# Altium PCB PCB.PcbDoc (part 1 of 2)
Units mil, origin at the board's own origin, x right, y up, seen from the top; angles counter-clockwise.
Board outline 4000 x 1900 mil, 2 copper layers (Top Layer, Bottom Layer), stack 62 mil thick; 73 components, 38 nets, 157 pads, 24 vias.
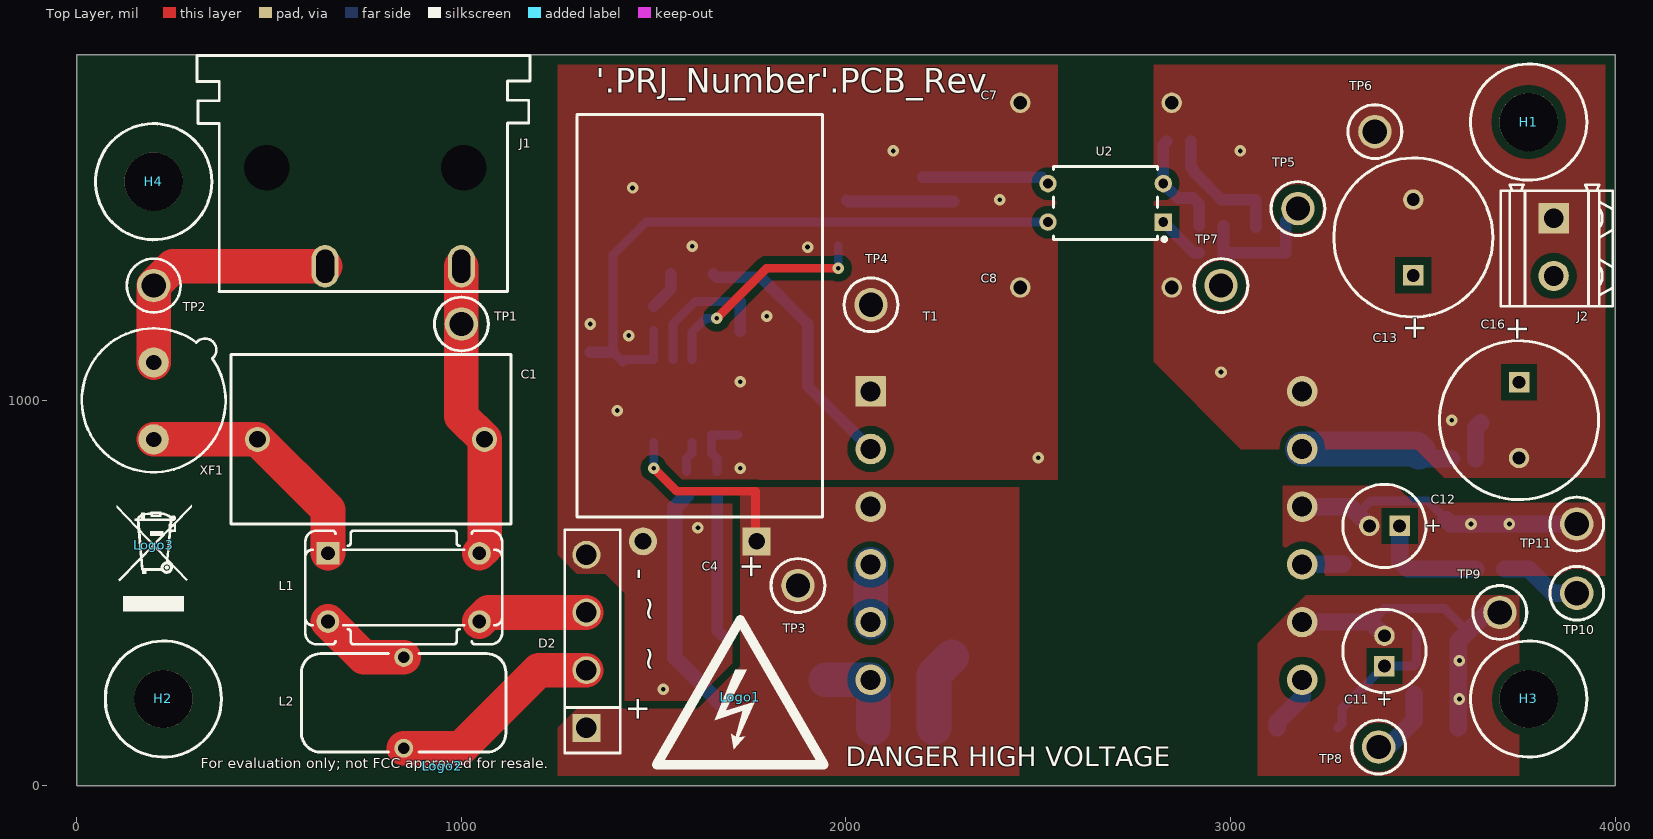
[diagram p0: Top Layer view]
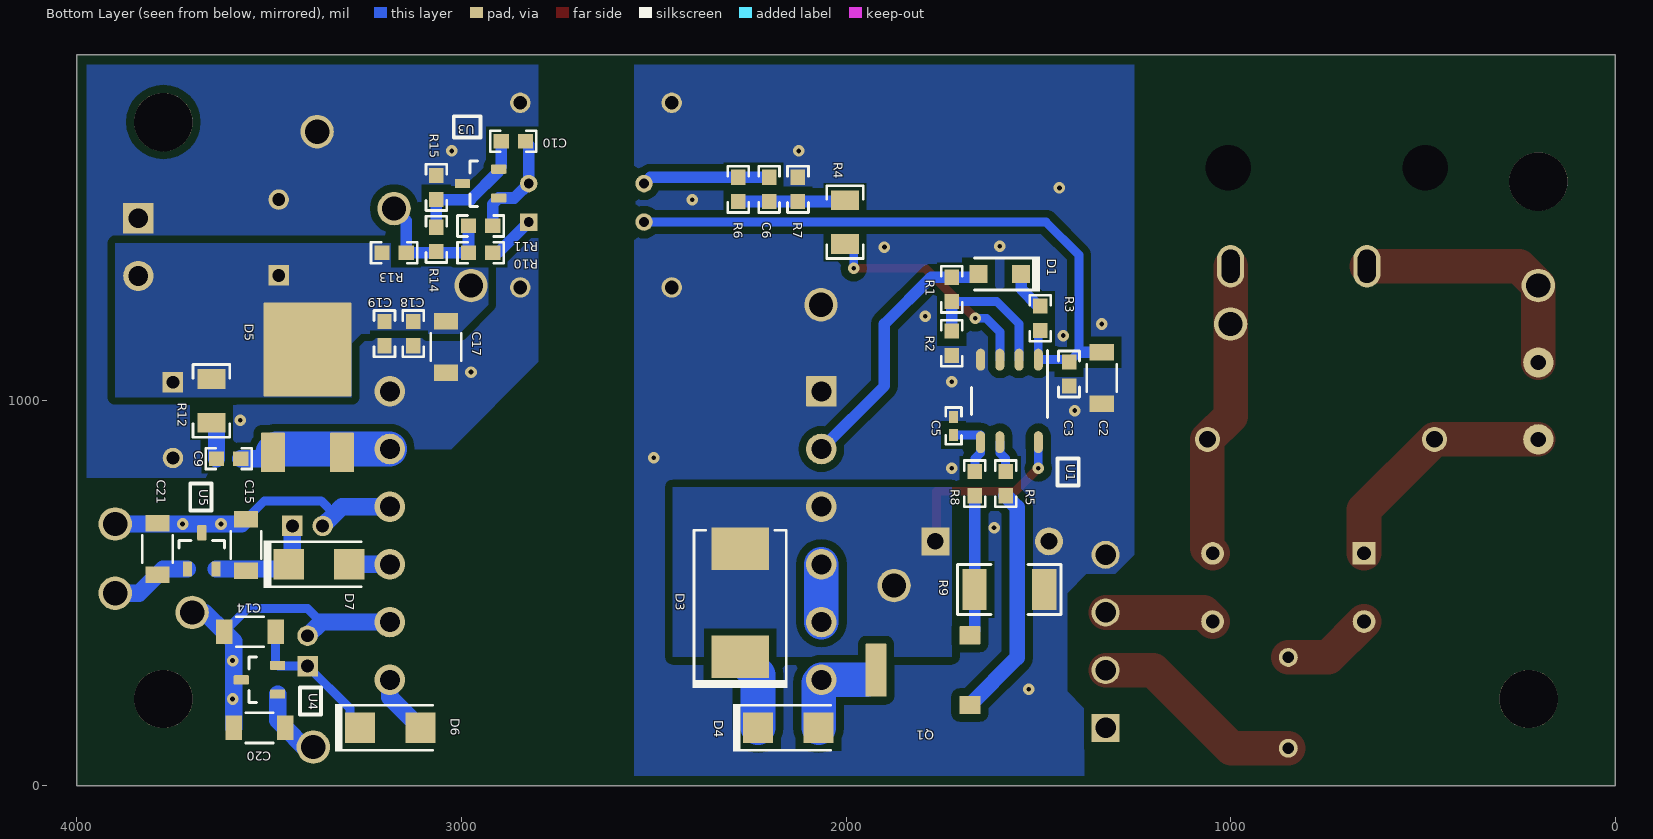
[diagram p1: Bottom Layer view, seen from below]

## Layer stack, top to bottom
Top Solder: solder mask 0.4, Solder Resist, Dk 3.5
Top Layer: signal copper 1.4
Dielectric1: core 59.2, FR-4, Dk 4.8
Bottom Layer: signal copper 1.4
Bottom Solder: solder mask 0.4, Solder Resist, Dk 3.5

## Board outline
0,0 4000,0 4000,1900 0,1900

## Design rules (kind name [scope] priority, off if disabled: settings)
AcuteAngle [All] p1: minimum=4.50000000000000E+0001 checktracksonly=FALSE
AssemblyTestPointUsage [All] p1: valid=2
BoardOutlineClearance BoardOutlineClearance_MountingHoles [OnCopper and InComponentClass('Mounting Holes')] p1: gap=25 ignorepadtopadclearanceinfootprint=FALSE
BoardOutlineClearance BoardOutlineClearance_Poly [OnCopper and InPoly] p2: gap=25 ignorepadtopadclearanceinfootprint=FALSE
BoardOutlineClearance [OnCopper and Not InComponentClass('Logo') and not InComponentClass('FiducialMark') and not InRegion(1000,500,4000,800)] p3: gap=25 ignorepadtopadclearanceinfootprint=FALSE
Clearance Clearance_2 [InNetClass('HV') vs Not InNetClass('HV')] p1: gap=60 ignorepadtopadclearanceinfootprint=FALSE
Clearance Clearance_1 [InNetClass('MV') vs Not InNetClass('MV')] p2: gap=30 ignorepadtopadclearanceinfootprint=FALSE
Clearance Clearance_Keepouts [((IsTrack Or IsArc) And Not InPoly) And IsFree and IsKeepOut vs ((IsTrack Or IsArc) And Not InPoly) And IsFree and IsKeepOut] p3: gap=0 ignorepadtopadclearanceinfootprint=FALSE
Clearance Clearance_BoardEdge_MountingHoles [OnCopper and InComponentClass('Mounting Holes') vs IsKeepOut] p4: gap=40 ignorepadtopadclearanceinfootprint=FALSE except(0: Arc-Hole Track-Hole SMDPad-Hole THPad-Hole Via-Hole Fill-Hole Poly-Hole Region-Hole Text-Hole)
Clearance Clearance_BoardEdge_Poly [OnCopper and InPoly vs IsKeepOut] p5: gap=50 ignorepadtopadclearanceinfootprint=FALSE except(0: Arc-Hole Track-Hole SMDPad-Hole THPad-Hole Via-Hole Fill-Hole Poly-Hole Region-Hole Text-Hole)
Clearance Clearance_BoardEdge [OnCopper and Not InComponentClass('Logo') and not InComponentClass('FiducialMark') and not InRegion(1000,500,4000,800) and Not IsKeepout vs IsKeepOut] p6: gap=50 ignorepadtopadclearanceinfootprint=FALSE
Clearance Clearance_Poly [InPolygon] p7: gap=20 ignorepadtopadclearanceinfootprint=FALSE except(0: Arc-Hole Track-Hole SMDPad-Hole THPad-Hole Via-Hole Fill-Hole Poly-Hole Region-Hole Text-Hole)
Clearance [All] p8: gap=7.87 ignorepadtopadclearanceinfootprint=FALSE except(0: Arc-Hole Track-Hole SMDPad-Hole THPad-Hole Via-Hole Fill-Hole Poly-Hole Region-Hole Text-Hole)
ComponentClearance ComponentClearance_MountingHoles_FiducialMarks [InComponentClass('Mounting Holes') vs InComponentClass('FiducialMark')] p1: gap=20 collisioncheckmode=3 verticalgap=10 showdistances=FALSE
ComponentClearance ComponentClearance_Shunt [InComponentClass('Header') vs InComponentClass('Shunt')] p2: gap=0 collisioncheckmode=3 verticalgap=0 showdistances=FALSE
ComponentClearance ComponentClearance_Logo [InComponentClass('Logo')] p3: gap=5 collisioncheckmode=3 verticalgap=10 showdistances=FALSE
ComponentClearance ComponentClearance_ScrewToNut [(HasFootprint('NY PMS 440 0025 PH')) vs (HasFootprint('Keystone_1902C'))] p4: gap=20 collisioncheckmode=3 verticalgap=100000 showdistances=FALSE
ComponentClearance ComponentClearance_MountingHoles [InComponentClass('Mounting Holes')] p5: gap=20 collisioncheckmode=3 verticalgap=10 showdistances=FALSE
ComponentClearance ComponentClearance_SmallPassives [HasFootprint('0201*') or HasFootprint('0402*') or HasFootprint('0508') or HasFootprint('0603*') or HasFootprint('0612') or HasFootprint('0805*') or HasFootprint('0815*') or HasFootprint('0830*') or HasFootprint('1206*') or HasFootprint('1210*') or HasFootprint('1808*') or HasFootprint('1812*') or HasFootprint('1825*') or HasFootprint('2010*') or HasFootprint('2220*') or HasFootprint('2225*') or HasFootprint('2512*') or HasFootprint('2728*') or HasFootprint('3518*') vs HasFootprint('0201*') or HasFootprint('0402*') or HasFootprint('0508') or HasFootprint('0603*') or HasFootprint('0612') or HasFootprint('0805*') or HasFootprint('0815*') or HasFootprint('0830*') or HasFootprint('1206*') or HasFootprint('1210*') or HasFootprint('1808*') or HasFootprint('1812*') or HasFootprint('1825*') or HasFootprint('2010*') or HasFootprint('2220*') or HasFootprint('2225*') or HasFootprint('2512*') or HasFootprint('2728*') or HasFootprint('3518*')] p6: gap=20 collisioncheckmode=3 verticalgap=20 showdistances=FALSE
ComponentClearance ComponentClearance_THtoSMT [IsThruComponent vs IsSMTComponent] p7: gap=10 collisioncheckmode=3 verticalgap=10 showdistances=FALSE
ComponentClearance ComponentClearance_THtoTH [IsThruComponent vs IsThruComponent] p8: gap=10 collisioncheckmode=3 verticalgap=10 showdistances=FALSE
ComponentClearance [All] p9: gap=10 collisioncheckmode=3 verticalgap=10 showdistances=FALSE
DiffPairsRouting [All] p1: maxlimit=100 minlimit=10 mostfreqgap=10 toplayer_minwidth=15 toplayer_maxwidth=15 toplayer_prefwidth=15 bottomlayer_minwidth=15 bottomlayer_maxwidth=15 bottomlayer_prefwidth=15 maxuncoupledlength=1000
FabricationTestPointUsage TestPointUsage [All] p1: valid=2 allowmultiple=FALSE
FabricationTestpoint Testpoint [All] p1: side=3 testpointundercomponent=TRUE minsize=40 maxsize=100 preferedsize=60 minholesize=0 maxholesize=40 preferedholesize=32 testpointgrid=1 allowsidetop=TRUE allowsidebottom=TRUE usegrid=TRUE gridtolerance=0.01
FanoutControl Fanout_LCC [IsLCC] p1: bgadir=Out bgaviamode=Centered fanoutstyle=Auto fanoutdirection=Alternating viagrid=1 // Fanout_LCC (Default Rule)
FanoutControl Fanout_BGA [IsBGA] p2: bgadir=Out bgaviamode=Centered fanoutstyle=Auto fanoutdirection=Alternating viagrid=1 // Fanout_BGA (Default Rule)
FanoutControl Fanout_Default [All] p4: bgadir=Out bgaviamode=Centered fanoutstyle=Auto fanoutdirection=Alternating viagrid=1 // Fanout_Default (Default Rule)
FanoutControl Fanout_Small [(CompPinCount < 5)] p5: bgadir=Out bgaviamode=Centered fanoutstyle=Auto fanoutdirection=OutThenIn viagrid=1 // Fanout_Small (Default Rule)
Height [All] p1: minheight=0 maxheight=3000 prefheight=500
HoleSize [All] p1: absolutevalues=TRUE maxlimit=251 minlimit=7.87 maxpercent=80.000 minpercent=20.000
MinimumAnnularRing MinimumAnnularRing_ThermalPadVias [IsVia and InAnyComponent] p1: minimumring=5.91
MinimumAnnularRing [All] p2: minimumring=8
MinimumSolderMaskSliver MinimumSolderMaskSliver_Logo [InComponentClass('Logo') vs InComponentClass('Logo')] p1: minsoldermaskwidth=0.7
MinimumSolderMaskSliver [All] p2: minsoldermaskwidth=3.94
PlaneConnect [All] p1: planeconnectstyle=Direct reliefexpansion=10 reliefentries=4 reliefconductorwidth=10 reliefairgap=10
PolygonConnect PolygonConnect_15 [All vs IsNamedPolygon('C109_2') Or  IsNamedPolygon('C107_2') Or  IsNamedPolygon('HV') Or  IsNamedPolygon('Q203_5') Or  IsNamedPolygon('C107_2') Or  IsNamedPolygon('HS') Or  IsNamedPolygon('Q201_5') Or  IsNamedPolygon('Q203_5') Or  IsNamedPolygon('C106_2') Or  IsNamedPolygon('C108_2') Or  IsNamedPolygon('Vout') Or  IsNamedPolygon('Q203_5') Or  IsNamedPolygon('C108_2') Or  IsNamedPolygon('C113_2') Or  IsNamedPolygon('Q203_5') Or  IsNamedPolygon('Q201_5') Or  IsNamedPolygon('C107_2') Or  IsNamedPolygon('C102_1') Or  IsNamedPolygon('SGND') Or  IsNamedPolygon('GND') Or  IsNamedPolygon('SGND') Or  IsNamedPolygon('GND') Or  IsNamedPolygon('IN+') Or  IsNamedPolygon('IN+') Or  IsNamedPolygon('Q201_5') Or  IsNamedPolygon('Q201_5') Or  IsNamedPolygon('SGND') Or  IsNamedPolygon('SGND') Or  IsNamedPolygon('Vout') Or  IsNamedPolygon('Vout') Or  IsNamedPolygon('IN+') Or  IsNamedPolygon('GND') Or  IsNamedPolygon('IN+') Or  IsNamedPolygon('GND')] p1: connectstyle=Direct reliefconductorwidth=10 reliefentries=4 polygonreliefangle="90 Angle" airgapwidth=10
PolygonConnect PolygonConnect_14 [All vs IsNamedPolygon('C106_2') Or  IsNamedPolygon('C107_2') Or  IsNamedPolygon('C107_2') Or  IsNamedPolygon('C107_2') Or  IsNamedPolygon('C102_1') Or  IsNamedPolygon('Q203_5') Or  IsNamedPolygon('Vout') Or  IsNamedPolygon('Q203_5') Or  IsNamedPolygon('Q203_5') Or  IsNamedPolygon('Q201_5') Or  IsNamedPolygon('C108_2') Or  IsNamedPolygon('Q203_5') Or  IsNamedPolygon('HS') Or  IsNamedPolygon('HV') Or  IsNamedPolygon('C108_2') Or  IsNamedPolygon('Q201_5') Or  IsNamedPolygon('C109_2') Or  IsNamedPolygon('Q201_5') Or  IsNamedPolygon('Q201_5') Or  IsNamedPolygon('C113_2')] p2: connectstyle=Direct reliefconductorwidth=10 reliefentries=4 polygonreliefangle="90 Angle" airgapwidth=10
PolygonConnect PolygonConnect_13 [All vs IsNamedPolygon('C102_1') Or  IsNamedPolygon('HV') Or  IsNamedPolygon('C107_2') Or  IsNamedPolygon('C109_2') Or  IsNamedPolygon('C107_2') Or  IsNamedPolygon('C108_2') Or  IsNamedPolygon('C106_2') Or  IsNamedPolygon('C108_2') Or  IsNamedPolygon('C113_2') Or  IsNamedPolygon('C107_2')] p3: connectstyle=Direct reliefconductorwidth=10 reliefentries=4 polygonreliefangle="90 Angle" airgapwidth=10
PolygonConnect PolygonConnect_12 [All vs IsNamedPolygon('C107_2') Or  IsNamedPolygon('C113_2') Or  IsNamedPolygon('C106_2') Or  IsNamedPolygon('C107_2') Or  IsNamedPolygon('C107_2') Or  IsNamedPolygon('C102_1')] p4: connectstyle=Direct reliefconductorwidth=10 reliefentries=4 polygonreliefangle="90 Angle" airgapwidth=10
PolygonConnect PolygonConnect_11 [All vs IsNamedPolygon('C106_2') Or  IsNamedPolygon('C102_1') Or  IsNamedPolygon('C107_2') Or  IsNamedPolygon('C107_2') Or  IsNamedPolygon('C107_2')] p5: connectstyle=Direct reliefconductorwidth=10 reliefentries=4 polygonreliefangle="90 Angle" airgapwidth=10
PolygonConnect PolygonConnect_10 [All vs IsNamedPolygon('C106_2')] p6: connectstyle=Direct reliefconductorwidth=10 reliefentries=4 polygonreliefangle="90 Angle" airgapwidth=10
PolygonConnect PolygonConnect_9 [All vs IsNamedPolygon('C11_1') Or  IsNamedPolygon('Vin') Or  IsNamedPolygon('Vin') Or  IsNamedPolygon('5V') Or  IsNamedPolygon('D6_2') Or  IsNamedPolygon('Q3_3') Or  IsNamedPolygon('GND2') Or  IsNamedPolygon('GND2') Or  IsNamedPolygon('GND') Or  IsNamedPolygon('Q3_4') Or  IsNamedPolygon('12V5') Or  IsNamedPolygon('GND') Or  IsNamedPolygon('12V5') Or  IsNamedPolygon('D3_1')] p7: connectstyle=Direct reliefconductorwidth=10 reliefentries=4 polygonreliefangle="90 Angle" airgapwidth=10
PolygonConnect PolygonConnect_8 [All vs IsNamedPolygon('C11_1') Or  IsNamedPolygon('Vin') Or  IsNamedPolygon('12V5') Or  IsNamedPolygon('Q3_3') Or  IsNamedPolygon('GND2') Or  IsNamedPolygon('GND2') Or  IsNamedPolygon('5V') Or  IsNamedPolygon('Q3_4') Or  IsNamedPolygon('12V5')] p8: connectstyle=Direct reliefconductorwidth=10 reliefentries=4 polygonreliefangle="90 Angle" airgapwidth=10
PolygonConnect PolygonConnect_7 [All vs IsNamedPolygon('GND2') Or  IsNamedPolygon('GND2') Or  IsNamedPolygon('5V') Or  IsNamedPolygon('12V5') Or  IsNamedPolygon('12V5') Or  IsNamedPolygon('C11_1')] p9: connectstyle=Direct reliefconductorwidth=10 reliefentries=4 polygonreliefangle="90 Angle" airgapwidth=10
PolygonConnect PolygonConnect_6 [All vs IsNamedPolygon('GND2') Or  IsNamedPolygon('SGND') Or  IsNamedPolygon('GND1') Or  IsNamedPolygon('C901_1') Or  IsNamedPolygon('SGND') Or  IsNamedPolygon('GND2') Or  IsNamedPolygon('GND1')] p10: connectstyle=Direct reliefconductorwidth=10 reliefentries=4 polygonreliefangle="90 Angle" airgapwidth=10
PolygonConnect PolygonConnect_5 [All vs IsNamedPolygon('GND1') Or  IsNamedPolygon('GND1')] p11: connectstyle=Direct reliefconductorwidth=10 reliefentries=4 polygonreliefangle="90 Angle" airgapwidth=10
PolygonConnect PolygonConnect_4 [All vs IsNamedPolygon('C21_1') Or  IsNamedPolygon('C5_1') Or  IsNamedPolygon('C12_2') Or  IsNamedPolygon('C2_2') Or  IsNamedPolygon('C13_1') Or  IsNamedPolygon('C28_1') Or  IsNamedPolygon('C6_1') Or  IsNamedPolygon('GND') Or  IsNamedPolygon('GND2') Or  IsNamedPolygon('C14_1') Or  IsNamedPolygon('C13_1') Or  IsNamedPolygon('Q1_3') Or  IsNamedPolygon('C14_1') Or  IsNamedPolygon('C5_1') Or  IsNamedPolygon('GND2') Or  IsNamedPolygon('C28_1') Or  IsNamedPolygon('D5_2') Or  IsNamedPolygon('D6_2') Or  IsNamedPolygon('D2_1') Or  IsNamedPolygon('C12_2') Or  IsNamedPolygon('D2_1') Or  IsNamedPolygon('C4_1') Or  IsNamedPolygon('C4_1') Or  IsNamedPolygon('C2_2') Or  IsNamedPolygon('GND') Or  IsNamedPolygon('C33_1') Or  IsNamedPolygon('C9_1')] p12: connectstyle=Direct reliefconductorwidth=10 reliefentries=4 polygonreliefangle="90 Angle" airgapwidth=10
PolygonConnect PolygonConnect_3 [All vs IsNamedPolygon('C28_1') Or  IsNamedPolygon('C12_2') Or  IsNamedPolygon('C28_1') Or  IsNamedPolygon('C9_1') Or  IsNamedPolygon('D5_2') Or  IsNamedPolygon('C12_2') Or  IsNamedPolygon('C2_2') Or  IsNamedPolygon('C14_1') Or  IsNamedPolygon('C4_1') Or  IsNamedPolygon('C14_1') Or  IsNamedPolygon('D6_2') Or  IsNamedPolygon('GND2') Or  IsNamedPolygon('Q1_3') Or  IsNamedPolygon('C5_1') Or  IsNamedPolygon('D2_1') Or  IsNamedPolygon('C4_1') Or  IsNamedPolygon('C13_1') Or  IsNamedPolygon('C5_1') Or  IsNamedPolygon('C13_1') Or  IsNamedPolygon('C33_1') Or  IsNamedPolygon('D2_1') Or  IsNamedPolygon('GND') Or  IsNamedPolygon('GND') Or  IsNamedPolygon('GND2') Or  IsNamedPolygon('C2_2') Or  IsNamedPolygon('C6_1') Or  IsNamedPolygon('C21_1')] p13: connectstyle=Direct reliefconductorwidth=10 reliefentries=4 polygonreliefangle="90 Angle" airgapwidth=10
PolygonConnect PolygonConnect_2 [All vs IsNamedPolygon('C21_1') Or  IsNamedPolygon('C4_1') Or  IsNamedPolygon('D5_2') Or  IsNamedPolygon('C5_1') Or  IsNamedPolygon('C14_1') Or  IsNamedPolygon('C13_1') Or  IsNamedPolygon('C4_1') Or  IsNamedPolygon('C33_1') Or  IsNamedPolygon('C12_2') Or  IsNamedPolygon('D2_1') Or  IsNamedPolygon('C2_2') Or  IsNamedPolygon('C28_1') Or  IsNamedPolygon('C12_2') Or  IsNamedPolygon('D2_1') Or  IsNamedPolygon('C5_1') Or  IsNamedPolygon('Q1_3') Or  IsNamedPolygon('GND') Or  IsNamedPolygon('D6_2') Or  IsNamedPolygon('C6_1') Or  IsNamedPolygon('C2_2') Or  IsNamedPolygon('C14_1') Or  IsNamedPolygon('C28_1') Or  IsNamedPolygon('C13_1') Or  IsNamedPolygon('C9_1') Or  IsNamedPolygon('GND')] p14: connectstyle=Direct reliefconductorwidth=10 reliefentries=4 polygonreliefangle="90 Angle" airgapwidth=10
PolygonConnect PolygonConnect_1 [All vs IsNamedPolygon('C28_1') Or  IsNamedPolygon('D5_2') Or  IsNamedPolygon('C5_1') Or  IsNamedPolygon('C5_1') Or  IsNamedPolygon('D2_1') Or  IsNamedPolygon('C21_1') Or  IsNamedPolygon('C9_1') Or  IsNamedPolygon('C4_1') Or  IsNamedPolygon('C14_1') Or  IsNamedPolygon('C28_1') Or  IsNamedPolygon('C6_1') Or  IsNamedPolygon('C12_2') Or  IsNamedPolygon('C33_1') Or  IsNamedPolygon('C4_1') Or  IsNamedPolygon('C13_1') Or  IsNamedPolygon('C12_2') Or  IsNamedPolygon('D6_2') Or  IsNamedPolygon('C2_2') Or  IsNamedPolygon('C14_1') Or  IsNamedPolygon('D2_1') Or  IsNamedPolygon('C2_2') Or  IsNamedPolygon('C13_1')] p15: connectstyle=Direct reliefconductorwidth=10 reliefentries=4 polygonreliefangle="90 Angle" airgapwidth=10
PolygonConnect [All] p16: connectstyle=Direct reliefconductorwidth=10 reliefentries=4 polygonreliefangle="90 Angle" airgapwidth=10
RoutingVias ThermalPadVias [IsVia and InAnyComponent] p1: holewidth=7.87 width=19.68 viastyle="Through Hole" minholewidth=7.87 minwidth=19.68 maxholewidth=12.99 maxwidth=23.62
RoutingVias [All] p2: holewidth=16 width=34 viastyle="Through Hole" minholewidth=7.87 minwidth=20 maxholewidth=40 maxwidth=65
SilkToBoardRegionClearance [Not ((IsComment or IsDesignator) And (Hide <> 'False')) and not InRegion(1000,500,4000,800)] p1:
SilkToSilkClearance SilkToSilkClearance_Pb-FreeLogo [(HasFootprint('Pb-Free_Overlay_Medium') OR HasFootprint('Pb-Free_Overlay_Small')) vs (HasFootprint('Pb-Free_Overlay_Medium') OR HasFootprint('Pb-Free_Overlay_Small'))] p1: silktosilkclearance=0
SilkToSilkClearance [All] p2: silktosilkclearance=4
SilkToSolderMaskClearance SilkToComponentPadClearance [IsPad and InAnycomponent] p1: minsilkscreentomaskgap=5 clearancetoexposedcopper=TRUE
SilkToSolderMaskClearance "Silk to Solder Mask Opening" [All] p2: minsilkscreentomaskgap=4 clearancetoexposedcopper=FALSE
SolderMaskExpansion [All] p1: expansion=1.97
Width [All] p1: maxlimit=100 minlimit=6 preferedwidth=10 checkconnectedcopper=TRUE
14 further rules are at their usual default settings.

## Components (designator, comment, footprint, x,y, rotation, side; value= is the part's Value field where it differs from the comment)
C1 "R474I310050A1K" Kemet_1800x1100x1900 765,900 r0 top value=0.1uF
C2 "CGA5L1X7R1H106K160AC" 1206_190 1335,1060 r270 bottom value=10uF
C3 "C1608X7R1E104K080AA" 0603 1420,1070 r90 bottom value=0.1uF
C4 "UCS2G470MHD" CAPPR7_5-16X25_HorizontalDown 1620,635 r180 top value=47uF
C5 "GRM155R71H331KA01D" 0402 1720,935 r90 bottom value=330pF
C6 "GRM188R71E473KA01D" 0603 2200,1550 r270 bottom value=0.047uF
C7 "VY1102M35Y5UQ63V0" VY1_900x500x1300 2650,1775 r180 top value=1000pF
C8 "VY1102M35Y5UQ63V0" VY1_900x500x1300 2650,1295 r180 top value=1000pF
C9 "GRM188R72A102KA01D" 0603 3605,850 r180 bottom value=1000pF
C10 "GRM188R71H221KA01D" 0603 2865,1675 r180 bottom value=220pF
C11 "EEUFC1C470" FC_500x1100 3400,350 r90 top value=47uF
C12 "EEUFC1C470" FC_500x1100 3400,675 r180 top value=47uF
C13 "EKZE160ELL471MJC5S" Chemi-Con_1000x1250 3475,1425 r90 top value=470uF
C14 "CGA5L1X7R1H106K160AC" 1206_190 3550,400 r0 bottom value=10uF
C15 "CGA5L1X7R1H106K160AC" 1206_190 3560,625 r90 bottom value=10uF
C16 "EKZE160ELL471MJC5S" Chemi-Con_1000x1250 3750,950 r270 top value=470uF
C17 "CGA5L1X7R1H106K160AC" 1206_190 3040,1140 r270 bottom value=10uF
C18 "C1608X7R1E104K080AA" 0603 3125,1175 r90 bottom value=0.1uF
C19 "C1608X7R1E104K080AA" 0603 3200,1175 r90 bottom value=0.1uF
C20 "CGA5L1X7R1H106K160AC" 1206_190 3525,150 r0 bottom value=10uF
C21 "CGA5L1X7R1H106K160AC" 1206_190 3790,615 r90 bottom value=10uF
D1 "PMEG10010ELRX" SOD-123W 1600,1330 r0 bottom value=100V
D2 "KBP06G" KBP 1325,375 r90 top value=600V
D3 "SMCJ200A" SMC 2275,475 r90 bottom value=200V
D4 "US1M-13-F" SMA 2150,150 r180 bottom value=1000V
D5 "MBRD10200CT-13" DPAK 3400,1000 r90 bottom value=200V
D6 "ES1D-13-F" SMA 3185,150 r180 bottom value=200V
D7 "ES1D-13-F" SMA 3370,575 r180 bottom value=200V
H1 "4826" KEYSTONE_4826 3775,1725 r0 top
H2 "4826" KEYSTONE_4826 225,225 r0 top
H3 "4826" KEYSTONE_4826 3775,225 r0 top
H4 "4826" KEYSTONE_4826 200,1570 r0 top
J1 "770W-X2/10" CONN_AC_770W-SERIES 750,1480 r0 top
J2 "691214310002" Wurth_691214310002 3840,1400 r270 top
L1 "744821150" WE-CMB_XS 850,515 r0 top value=5mH
L2 "7447031" WE-FI_1350x700 850,215 r270 top value=140uH
Logo1 "DANGER HIGH VOLTAGE" IEC_HighVoltage_Medium 1725,230 r0 top (schematic designator LOGO1)
Logo2 "FCC disclaimer" FCC_disclaimer 950,50 r0 top
Logo3 "WEEE logo" WEEE_Minimum 200,625 r0 top
Q1 "IPN70R360P7SATMA1" PG-SOT223 1800,300 r0 bottom value=700V
R1 "CRCW060347K5FKEA" 0603 1725,1290 r90 bottom value=47.5k
R2 "CRCW060328K7FKEA" 0603 1725,1150 r90 bottom value=28.7k
R3 "CRCW06031R00JNEA" 0603 1495,1215 r270 bottom value=1.0
R4 "CRCW12060000Z0EA" 1206 2002.5,1465 r270 bottom value=0
R5 "CRCW060310R0JNEA" 0603 1585,785 r270 bottom value=10
R6 "CRCW0603100KFKEA" 0603 2280,1550 r90 bottom value=100k
R7 "CRCW060322K1FKEA" 0603 2125,1550 r270 bottom value=22.1k
R8 "CRCW06032K15FKEA" 0603 1665,785 r270 bottom value=2.15k
R9 "CSRN2010FKR750" 2010 1575,510 r0 bottom value=0.75
R10 "CRCW06031K50FKEA" 0603 2950,1385 r0 bottom value=1.50k
R11 "CRCW060310K0FKEA" 0603 2950,1455 r0 bottom value=10.0k
R12 "CRCW1206200RJNEA" 1206 3650,1000 r270 bottom value=200
R13 "CRCW06030000Z0EA" 0603 3175,1385 r0 bottom value=0
R14 "CRCW0603909KFKEA" 0603 3065,1420 r270 bottom value=909k
R15 "CRCW0603178KFKEA" 0603 3065,1555 r270 bottom value=178k
T1 "750318302" FP-750318302_TRANS_PTH_33MM0_26MM3-MFG 2625,650 r0 top
TP1 "5012" Keystone5012 1000,1200 r180 top
TP2 "5125" Keystone5125 200,1300 r180 top
TP3 "5010" Keystone5010 1875,520 r0 top
TP4 "5011" Keystone5011 2065,1250 r0 top
TP5 "5014" Keystone5014 3175,1500 r0 top
TP6 "5011" Keystone5011 3375,1700 r0 top
TP7 "5010" Keystone5010 2975,1300 r0 top
TP8 "5010" Keystone5010 3385,100 r0 top
TP9 "5011" Keystone5011 3700,450 r0 top
TP10 "5010" Keystone5010 3900,500 r0 top
TP11 "5011" Keystone5011 3900,680 r0 top
U1 "UCC28711DR" D0007A_N 1575,1000 r270 bottom
U2 "VO618A-3" DIP-4 2675,1515 r180 top
U3 "ATL431AIDBZR" DBZ0003A_N 2950,1565 r0 bottom
U4 "TLV76015DBZR" DBZ0003A_N 3525,275 r0 bottom
U5 "TLV76015DBZR" DBZ0003A_N 3675,610 r90 bottom
XF1 "56000001009" FuseHolder_560000010 200,1000 r90 top value=TR5

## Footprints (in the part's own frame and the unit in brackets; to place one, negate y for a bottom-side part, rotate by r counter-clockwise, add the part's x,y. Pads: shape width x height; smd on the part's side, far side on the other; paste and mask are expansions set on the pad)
0402 [mm] "0402 from SM-752 data"
  rect 0.8x0.6 smd: 1(-0.6,0) 2(0.6,0)
  silkscreen extent -1.22,-0.52 1.22,0.52, body extent -0.55,-0.3 0.55,0.3, height 0.6
0603 [mm] "0603 from SM-752 data"
  rect 1x0.95 smd: 1(-0.8,0) 2(0.8,0)
  silkscreen extent -1.52,-0.69 1.52,0.69, body extent -0.87,-0.47 0.87,0.47, height 1
1206 [mm] "1206 from SM-752 data"
  rect 1.3x1.85 smd: 1(-1.45,0) 2(1.45,0)
  silkscreen extent -2.4,-1.21 2.4,1.21, body extent -1.7,-0.9 1.7,0.9, height 1.35
1206_190 [mm] "1206_190"
  rect 1.1x1.6 smd: 1(-1.7,0) 2(1.7,0)
  silkscreen extent -0.9,-1 0.9,1, body extent -1.75,-0.95 1.75,0.95, height 1.9
2010 [mm] "Chip Capacitor, Body 5.08x2.54mm, IPC Medium Density"
  rect 1.6x2.7 smd: 1(-2.3,0) 2(2.3,0)
  silkscreen extent -3.42,-1.65 3.42,1.65, body extent -2.73,-1.45 2.73,1.45, height 1.66
CAPPR7_5-16X25_HorizontalDown [mm] "Capacitor, Electrolytic, Radial; Body 16 x 25 mm (Dia.xH typ); Pin Spacing 7.5 mm (typ)"
  rect 1.85x1.85 hole 1.1: 1(-3.75,0)
  round 1.85 hole 1.1: 2(3.75,0)
  silkscreen extent -8.1,-28.18 8.1,-1.6, body extent -8.11,-28.2 8.3,0.5, height 16.24
Chemi-Con_1000x1250 [mm] "TH, 2-Leads, Body 10x12.5mm, Pin Spacing 5mm"
  rect 1.35x1.35 hole 0.85: 1(-2.5,0)
  round 1.35 hole 0.85: 2(2.5,0)
  silkscreen extent -5.25,-5.25 5.25,5.25, body extent -5.25,-5.25 5.25,5.25, height 14
CONN_AC_770W-SERIES [mm] "Qualtek Electronics"
  oval 1.8x2.8 hole 1.2 slot 2.2 at 90 deg: 1(6.35,-3.3) 2(-2.65,-3.3)
  round 2 hole 3 unplated: MH1(6.5,3.2) MH2(-6.5,3.2)
  silkscreen extent -11.12,-4.97 10.87,10.63, body extent -11.05,-4.8 10.8,10.6, height 22
D0007A_N [mm] "SOIC, 7-Leads, Body 4.9x3.9mm, Pitch 1.27mm, IPC Medium Density"
  oval 1.45x0.6 smd: 1(-2.725,1.905) 2(-2.725,0.635) 3(-2.725,-0.635) 4(-2.725,-1.905) 5(2.725,-1.905) 6(2.725,-0.635) 8(2.725,1.905)
  silkscreen extent -3.32,-2.5 1.1,2.52, body extent -3.01,-2.45 3.01,2.45, height 1.75
DBZ0003A_N [mm] "SOT23, 3-Leads, Body 2.9x1.3mm, Pitch 0.95mm, Lead Span 2.4mm, IPC Medium Density"
  rrect17% 1x0.6 smd: 1(-1.2,0.95) 2(-1.2,-0.95) 3(1.2,0)
  silkscreen extent 0.2,-1.5 0.7,1.5, body extent -1.26,-1.46 1.26,1.46, height 0.98
DIP-4 [mm] "DIP, 4-Leads, Body 6.86x4.83mm, Pitch 2.54mm"
  rect 1.15x1.15 hole 0.65: 1(-3.81,1.27)
  round 1.15 hole 0.65: 2(-3.81,-1.27) 3(3.81,-1.27) 4(3.81,1.27)
  silkscreen extent -4,-2.41 3.43,2.52, body extent -4.02,-2.41 4.02,2.41, height 5.59
DPAK [mm] "D-PAK, 3-Pads, Body 6.22x6.73mm (max), TO-252AA using nominal STEP model"
  rrect6% 2.6x1.6 smd: 1(-3.4,2.28) 3(-3.4,-2.28)
  rrect2% 6.2x5.8 smd paste-3: 2(3.4,0)
  body extent -3.86,-3.29 5.84,3.29, height 2.48
FC_500x1100 [mm] "TH, 2-Leads, Dia 5mm,  Lead Spacing 2mm"
  rect 1.35x1.35 hole 0.85: 1(-1,0)
  round 1.35 hole 0.85: 2(1,0)
  silkscreen extent -2.75,-2.75 2.75,2.75, body extent -2.73,-2.75 2.75,2.75, height 12.51
FCC_disclaimer [mil]
FP-750318302_TRANS_PTH_33MM0_26MM3-MFG [mm]
  rrect5% 2.02x2.02 hole 1.32 paste-1000 mask+0: 1(-14.25,9.525)
  round 2.02 hole 1.32 paste-1000 mask+0: 2(-14.25,5.715) 3(-14.25,1.905) 4(-14.25,-1.905) 5(-14.25,-5.715) 6(-14.25,-9.525) 7(14.25,-9.525) 8(14.25,-5.715) 9(14.25,-1.905) 10(14.25,1.905) 11(14.25,5.715) 12(14.25,9.525)
  body extent -16.6,-13.25 16.6,13.25, height 0.25
FuseHolder_560000010 [mm] "Littelfuse fuse holder TR5"
  round 2 hole 1: 1(-2.54,0) 2(2.54,0)
  silkscreen extent -4.71,-4.75 4.79,4.75, body extent -4.75,-4.74 4.75,4.75, height 5.6
IEC_HighVoltage_Medium [mil]
  silkscreen extent -217,-176 217,200
KBP [mm] "Diodes Inc Bridge Rectifier"
  rect 1.85x1.85 hole 1.35: 1(-5.715,0)
  round 1.85 hole 1.35: 2(-1.905,0) 3(1.905,0) 4(5.715,0)
  silkscreen extent -7.37,-2.23 7.38,1.42, body extent -7.37,-2.23 7.38,1.42, height 12.91
Kemet_1800x1100x1900 [mm] "TH, 2-Leads, Body 18x11mm, Pin Spacing 15mm"
  round 1.65 hole 1.1: 1(-7.5,0) 2(7.5,0)
  silkscreen extent -9.25,-5.6 9.25,5.6, body extent -9.25,-5.6 9.25,5.6, height 19.1
Keystone5010 [mil] "Keystone Multipurpose loops"
  round 87 hole 63: 1(0,0)
  silkscreen extent -70,-70 70,70, body extent -63,-63 63,62, height 319
Keystone5011 [mil] "Keystone Multipurpose loops"
  round 87 hole 63: 1(0,0)
  silkscreen extent -70,-70 70,70, body extent -63,-63 63,62, height 319
Keystone5012 [mil] "Keystone Multipurpose loops"
  round 87 hole 63: 1(0,0)
  silkscreen extent -70,-70 70,70, body extent -63,-63 63,62, height 319
Keystone5014 [mil] "Keystone Multipurpose loops"
  round 87 hole 63: 1(0,0)
  silkscreen extent -70,-70 70,70, body extent -63,-63 63,62, height 319
Keystone5125 [mil] "Keystone Multipurpose loops"
  round 87 hole 63: 1(0,0)
  silkscreen extent -70,-70 70,70, body extent -63,-63 63,62, height 319
KEYSTONE_4826 [mil] "HEX STANDOFF 6-32 NYLON 1750 mil"
  round 1 on Mech3: 0(0,0)
  round 152 hole 152 unplated: MH(0,0)
  silkscreen extent -151,-151 151,151, body extent -144,-125 144,125, height 1751
PG-SOT223 [mm] "SMD, 3-Leads, Body 7x6.5mm"
  rrect8% 1.4x1.2 smd: 1(-3.1,2.3) 3(-3.1,-2.3)
  rrect7% 1.4x3.5 smd: 2(3.1,0)
  body extent -3.5,-3.25 3.5,3.25, height 1.8
SMA [mm] "Molded Diode, 2-Leads, Body 4.3x2.6mm, IPC Medium Density, based on OnSemi component dimensions and land pattern"
  rect 2x2 smd: 1(-2,0) 2(2,0)
  silkscreen extent -3.66,-1.57 2.79,1.57, body extent -2.6,-1.3 2.6,1.3, height 2.42
SMC [mil] "Molded Diode, 2-Leads, Body 6.9x5.8mm, IPC Medium Density, based on OnSemi component dimensions and land patterns"
  rect 110x150 smd: 1(-140.49,0) 2(140.49,0)
  silkscreen extent -221,-123 189,124, body extent -156,-116 156,116, height 91
SOD-123W [mm] "NXP recommended land pattern"
  rect 1.2x1.2 smd paste-0.05: 1(-1.4,0) 2(1.4,0)
  silkscreen extent -2.64,-1.14 1.68,1.14, body extent -1.85,-0.95 1.85,0.95, height 1.1
VY1_900x500x1300 [mm] "TH, Body 9x5mm, PinSpacing 10mm"
  round 1.35 hole 0.9: 1(-5,0) 2(5,0)
  body extent -5.4,-2.5 5.4,2.5, height 12.93
WE-CMB_XS [mm] "WE-CMB Series Size XS"
  rect 1.5x1.5 hole 0.9: 1(-5,2.25)
  round 1.5 hole 0.9: 2(-5,-2.25) 3(5,-2.25) 4(5,2.25)
  silkscreen extent -6.5,-3.75 6.5,3.75, body extent -6.5,-3.75 6.5,3.75, height 16.24
WE-FI_1350x700 [mm] "TH, 2-Leads, Dia 13.5mm"
  round 1.25 hole 0.75: 1(-3,0) 2(3,0)
  silkscreen extent -3.25,-6.75 3.25,6.75, body extent -3.25,-6.75 3.25,6.75, height 13.32
WEEE_Minimum [mil] "WEEElie bin"
  silkscreen extent -95,-172 99,104
Wurth_691214310002 [mm] "WE"
  rect 2x2 hole 1.3: 1(-1.905,0)
  round 2 hole 1.3: 2(1.905,0)
  silkscreen extent -4.12,-3.5 3.9,3.9, body extent -4.12,-3.5 3.9,3.9, height 8.52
